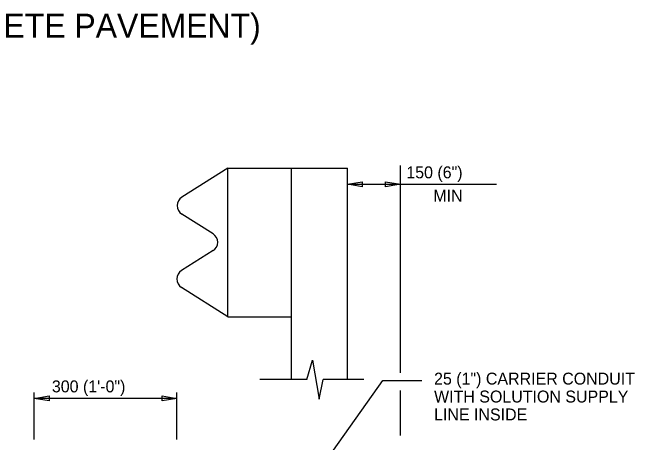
# Model space of a CAD drawing. Extents: x 3239 to 4230, y -4276 to -2494.
# Drawn here: x 3574.2 to 3730.5, y -3391.8 to -3283.7 of the extents above; entities that cross this region are included whole.
import ezdxf

# ---------------------------------------------------------------- set-up
doc = ezdxf.new("R2010")
doc.units = 0
doc.layers.add('2', color=7, linetype='Continuous')

msp = doc.modelspace()

# ---------------------------------------------------------------- linework, layer by layer
at = {"layer": '2'}
for p, q in [((3671.69, -3374.22), (3671.69, -3322.12)), ((3628.38, -3322.79), (3616.78, -3330.12)), ((3628.38, -3322.79), (3658.38, -3322.79)), ((3628.38, -3360.17), (3628.38, -3322.79)), ((3644.38, -3375.88), (3644.38, -3322.79)), ((3658.38, -3375.88), (3658.38, -3322.79)), ((3658.38, -3326.88), (3695.82, -3326.88)), ((3624.64, -3339.32), (3616.78, -3334.35)), ((3624.64, -3343.54), (3616.7, -3348.56)), ((3628.38, -3360.17), (3616.7, -3352.79)), ((3628.38, -3360.17), (3644.38, -3360.17)), ((3648.17, -3375.88), (3636.37, -3375.88)), ((3662.54, -3375.88), (3652.26, -3375.88)), ((3671.69, -3389.95), (3671.69, -3378.67)), ((3579.7, -3391.01), (3579.7, -3379.15)), ((3615.58, -3391.01), (3615.58, -3379.15)), ((3615.58, -3380.65), (3579.7, -3380.65))]:
    msp.add_line(p, q, dxfattribs=at)
for points in [[(3662.13, -3327.51), (3658.38, -3326.88), (3662.13, -3326.25)], [(3667.94, -3326.25), (3671.69, -3326.88), (3667.94, -3327.51)], [(3583.45, -3381.28), (3579.7, -3380.65), (3583.45, -3380.02)], [(3611.83, -3380.02), (3615.58, -3380.65), (3611.83, -3381.28)]]:
    msp.add_lwpolyline(points, close=True, dxfattribs=at)
for points in [[(3648.17, -3375.88), (3649.64, -3371.06), (3651.28, -3380.82), (3652.26, -3375.88)], [(3637.78, -3417.8), (3667.31, -3376.16), (3677.08, -3376.16)]]:
    msp.add_lwpolyline(points, dxfattribs=at)
for centre, start, end in [((3618.12, -3332.23), 122.3108, 237.6892), ((3623.3, -3341.43), 302.3108, 57.6892), ((3618.04, -3350.67), 122.3108, 237.6892)]:
    msp.add_arc(centre, 2.5, start, end, dxfattribs=at)

# ---------------------------------------------------------------- texts
for s, height, p in [('(NEW APPROACH CONCRETE PAVEMENT)', 6, (3471.68, -3290.03)), ('150 (6")', 3, (3673.19, -3325.38)), ('MIN', 3, (3679.98, -3331.27)), ('25 (1") CARRIER CONDUIT', 3, (3680.16, -3377.2)), ('300 (1\'-0")', 3, (3584.15, -3379.15)), ('WITH SOLUTION SUPPLY', 3, (3680.16, -3381.7)), ('LINE INSIDE', 3, (3680.16, -3386.2))]:
    msp.add_text(s, height=height, dxfattribs=at).set_placement(p)

doc.saveas('drawing.dxf')
